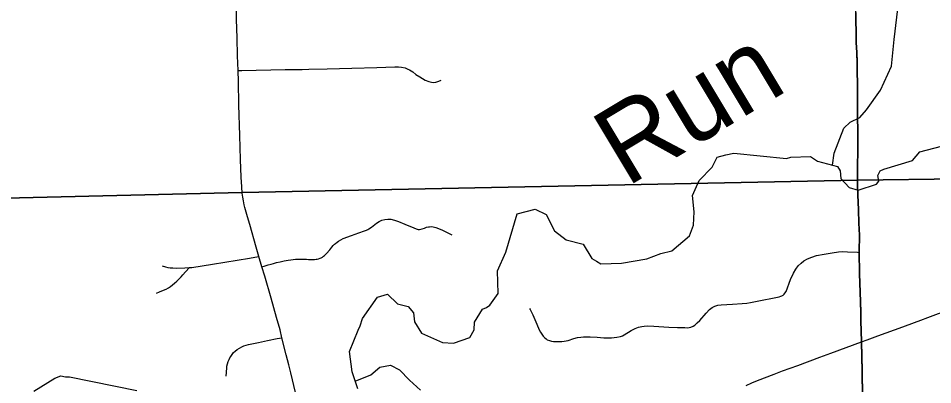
# Model space of a CAD drawing. Extents: x -6.4 to 34, y -4.2 to 22.
# Drawn here: x 5.927 to 7.044, y 20.413 to 20.86 of the extents above; entities that cross this region are included whole.
import ezdxf

# ---------------------------------------------------------------- set-up
doc = ezdxf.new("R2010")
doc.units = 0
for name, color, linetype in [('GM_X_Corporation', 7, 'Continuous'), ('GM_X_County_Road', 7, 'Continuous'), ('GM_X_Minor_River', 7, 'Continuous'), ('GM_X_Minor_River_Text', 7, 'Continuous'), ('GM_X_Township_Road', 7, 'Continuous')]:
    doc.layers.add(name, color=color, linetype=linetype)

msp = doc.modelspace()

# ---------------------------------------------------------------- linework, layer by layer
at = {"layer": 'GM_X_Corporation'}
for points in [[(5.4344, 20.629), (6.2003, 20.6471), (6.9525, 20.6623), (6.9525, 20.6735), (6.9527, 20.7036), (6.9526, 20.7219), (6.9525, 20.7397), (6.9524, 20.7675), (6.9522, 20.78), (6.9519, 20.7949), (6.9517, 20.8061), (6.9513, 20.8179), (6.9508, 20.8304), (6.9505, 20.8437), (6.9503, 20.8563), (6.9501, 20.8668), (6.9499, 20.8761), (6.9496, 20.886), (6.9493, 20.8922), (6.9492, 20.8965), (6.9491, 20.9), (2.1, 20.9)], [(6.9501, 20.8668), (6.9503, 20.8563), (6.9505, 20.8437), (6.9508, 20.8304), (6.9513, 20.8179), (6.9517, 20.8061), (6.9519, 20.7949), (6.9522, 20.78), (6.9524, 20.7675), (6.9525, 20.7397), (6.9526, 20.7219), (6.9527, 20.7036), (6.9525, 20.6735), (6.9525, 20.6623), (7.3276, 20.6671)], [(6.9584, 20.3986), (6.9578, 20.429), (6.9571, 20.4653), (6.9564, 20.4906), (6.9562, 20.5009), (6.9558, 20.514), (6.9549, 20.5481), (6.9545, 20.5746), (6.9546, 20.5952), (6.9541, 20.6099), (6.9535, 20.6262), (6.9528, 20.6443), (6.9525, 20.6571), (6.9525, 20.6623), (6.2003, 20.6471), (5.4344, 20.629)], [(7.3276, 20.6671), (6.9525, 20.6623), (6.9525, 20.6571), (6.9528, 20.6443), (6.9535, 20.6262), (6.9541, 20.6099), (6.9546, 20.5952), (6.9545, 20.5746), (6.9549, 20.5481), (6.9558, 20.514), (6.9562, 20.5009), (6.9564, 20.4906), (6.9571, 20.4653), (6.9578, 20.429), (6.9584, 20.3986)]]:
    msp.add_lwpolyline(points, dxfattribs=at)
at = {"layer": 'GM_X_County_Road'}
for points in [[(7.033, 20.4926), (7.0348, 20.4933), (7.0686, 20.506), (7.1085, 20.5212), (7.1624, 20.5408), (7.1749, 20.5452), (7.1812, 20.5473), (7.1875, 20.5496), (7.1944, 20.5522), (7.2027, 20.5556), (7.2113, 20.5597), (7.2192, 20.5638), (7.2292, 20.5695), (7.2385, 20.5759), (7.248, 20.582), (7.2572, 20.5884), (7.2748, 20.6012), (7.2872, 20.61), (7.2985, 20.6173), (7.3094, 20.6239), (7.3208, 20.6298), (7.329, 20.6338), (7.3327, 20.6357), (7.3446, 20.6412)], [(6.9573, 20.4647), (6.9643, 20.4673), (6.9771, 20.4721), (7.0075, 20.4831), (7.033, 20.4926)], [(6.8164, 20.4115), (6.823, 20.4147), (6.8301, 20.4176), (6.8503, 20.4255), (6.8608, 20.4294), (6.8795, 20.4362), (6.9063, 20.4462), (6.9198, 20.4511), (6.9573, 20.4647)]]:
    msp.add_lwpolyline(points, dxfattribs=at)
at = {"layer": 'GM_X_Minor_River'}
for points in [[(6.9218, 20.6806), (6.9238, 20.6952), (6.9354, 20.7258), (6.9433, 20.7331), (6.9553, 20.7387), (6.9635, 20.7479), (6.9805, 20.7721), (6.9937, 20.8016), (6.9969, 20.8339), (7.0043, 20.8959), (7.0061, 20.9)], [(6.5822, 20.6006), (6.5964, 20.5895), (6.6169, 20.5841), (6.6278, 20.5668), (6.6332, 20.5635), (6.6385, 20.5602), (6.6639, 20.561), (6.6949, 20.5664), (6.7122, 20.5728), (6.7254, 20.5761), (6.7471, 20.5943), (6.7521, 20.6073), (6.7526, 20.6236), (6.7508, 20.6437), (6.7588, 20.6617), (6.7749, 20.6783), (6.7807, 20.6902), (6.7913, 20.693), (6.8011, 20.6951), (6.8656, 20.6886), (6.8709, 20.6902), (6.8947, 20.6913), (6.9035, 20.6854), (6.9279, 20.679), (6.9313, 20.6737), (6.9319, 20.6642), (6.9423, 20.6534), (6.9533, 20.6502), (6.9755, 20.6574), (6.9785, 20.6612), (6.9773, 20.668), (6.9798, 20.6738), (6.9843, 20.6757), (7.0194, 20.6862), (7.0283, 20.697), (7.0551, 20.7039)], [(6.3418, 20.4075), (6.335, 20.4283), (6.3316, 20.4529), (6.3421, 20.4793), (6.3447, 20.4846), (6.3476, 20.4934), (6.3657, 20.5195), (6.3782, 20.5232), (6.3901, 20.5112), (6.4034, 20.508), (6.4096, 20.5002), (6.4109, 20.4892), (6.4195, 20.4756), (6.4454, 20.4639), (6.4587, 20.4634), (6.4786, 20.4702), (6.4838, 20.4797), (6.4844, 20.4889), (6.494, 20.5046), (6.4989, 20.507), (6.503, 20.5097), (6.5134, 20.5239), (6.5125, 20.5516), (6.5228, 20.5742), (6.5364, 20.6211), (6.5583, 20.6268), (6.5717, 20.6202), (6.5822, 20.6006)], [(6.3387, 20.417), (6.3578, 20.4245), (6.3686, 20.4338), (6.3815, 20.4363), (6.3925, 20.4308), (6.4049, 20.4181), (6.4183, 20.4061)], [(5.946, 20.4047), (5.9715, 20.4207), (5.9787, 20.4235), (5.9844, 20.422), (5.9893, 20.4221), (6.0718, 20.4053)]]:
    msp.add_lwpolyline(points, dxfattribs=at)
at = {"layer": 'GM_X_Township_Road'}
for points in [[(6.2005, 20.6465), (6.2001, 20.654), (6.1994, 20.6658), (6.1986, 20.6876), (6.1976, 20.7167), (6.1965, 20.754), (6.1958, 20.7825), (6.1955, 20.796), (6.1948, 20.8141), (6.1942, 20.8359), (6.1936, 20.8584), (6.193, 20.8795), (6.1924, 20.9)], [(6.9527, 20.6618), (6.9527, 20.6729), (6.9529, 20.703), (6.9528, 20.7213), (6.9527, 20.7392), (6.9526, 20.7669), (6.9523, 20.7795), (6.9521, 20.7944), (6.9519, 20.8055), (6.9515, 20.8173), (6.951, 20.8298), (6.9507, 20.8431), (6.9505, 20.8557), (6.9503, 20.8663), (6.9501, 20.8756), (6.9498, 20.8855), (6.9495, 20.8917), (6.9494, 20.896), (6.9493, 20.9)], [(6.1955, 20.796), (6.2001, 20.7962), (6.2531, 20.7975), (6.2739, 20.7975), (6.2819, 20.7976), (6.3045, 20.7983), (6.3345, 20.7991), (6.365, 20.7999), (6.3868, 20.8005), (6.3913, 20.8004), (6.3951, 20.8001), (6.3996, 20.7992), (6.4029, 20.7979), (6.4048, 20.7969), (6.4089, 20.7943), (6.4128, 20.7914), (6.4175, 20.7883), (6.424, 20.7845), (6.4286, 20.7826), (6.4316, 20.7818), (6.434, 20.7816), (6.4371, 20.7819), (6.4407, 20.783), (6.4435, 20.7843)], [(6.9573, 20.4647), (6.9566, 20.4901), (6.9564, 20.5004), (6.956, 20.5134), (6.9551, 20.5476), (6.9547, 20.5741), (6.9548, 20.5946), (6.9543, 20.6094), (6.9537, 20.6257), (6.953, 20.6437), (6.9527, 20.6565), (6.9527, 20.6618)], [(6.2685, 20.3896), (6.2655, 20.4032), (6.2599, 20.4269), (6.2573, 20.4369), (6.2541, 20.4489), (6.249, 20.4698), (6.2467, 20.4795), (6.2425, 20.4947), (6.236, 20.5181), (6.228, 20.5449), (6.2244, 20.5563), (6.2209, 20.5689), (6.2177, 20.5806), (6.2098, 20.6081), (6.2071, 20.6175), (6.2038, 20.629), (6.203, 20.6322), (6.2019, 20.6369), (6.2011, 20.6416), (6.2005, 20.6465)], [(6.2244, 20.5563), (6.2272, 20.5572), (6.2324, 20.5589), (6.2358, 20.5599), (6.2387, 20.5607), (6.2422, 20.5617), (6.2468, 20.5626), (6.2516, 20.5636), (6.2566, 20.5645), (6.2599, 20.565), (6.2657, 20.5657), (6.2685, 20.5659), (6.2722, 20.566), (6.2761, 20.5659), (6.2792, 20.5657), (6.2813, 20.5656), (6.2838, 20.5654), (6.2872, 20.5655), (6.2889, 20.5655), (6.2908, 20.5657), (6.292, 20.566), (6.2938, 20.5664), (6.2957, 20.5671), (6.297, 20.5676), (6.2985, 20.5684), (6.2997, 20.5693), (6.301, 20.5702), (6.3034, 20.5726), (6.3077, 20.5773), (6.3102, 20.5805), (6.3117, 20.5823), (6.3134, 20.5841), (6.3144, 20.5849), (6.3166, 20.5866), (6.3182, 20.5878), (6.3209, 20.5895), (6.3239, 20.5909), (6.3341, 20.5948), (6.3428, 20.598), (6.3499, 20.6005), (6.3522, 20.6013), (6.354, 20.6022), (6.3552, 20.6029), (6.3584, 20.6048), (6.3647, 20.6099), (6.3679, 20.6119), (6.3712, 20.6133), (6.3748, 20.6143), (6.3785, 20.6147), (6.3822, 20.6145), (6.3864, 20.6136), (6.3916, 20.6116), (6.3991, 20.6086), (6.4103, 20.6041), (6.4129, 20.6029), (6.4142, 20.6024), (6.4155, 20.6021), (6.4163, 20.602), (6.4172, 20.6021), (6.4188, 20.6025), (6.4203, 20.6029), (6.4232, 20.6038), (6.4257, 20.6047), (6.4281, 20.6051), (6.4293, 20.6054), (6.4314, 20.6056), (6.4338, 20.6052), (6.437, 20.6045), (6.4404, 20.6034), (6.4452, 20.6012), (6.4568, 20.5954)], [(6.5515, 20.5055), (6.5522, 20.5045), (6.5554, 20.4977), (6.5604, 20.4864), (6.5635, 20.4796), (6.5648, 20.4767), (6.5664, 20.4742), (6.5682, 20.4718), (6.5697, 20.4701), (6.5718, 20.4685), (6.5733, 20.4675), (6.5761, 20.4665), (6.5784, 20.4659), (6.5809, 20.4655), (6.5835, 20.4653), (6.5877, 20.4653), (6.5912, 20.4654), (6.594, 20.4657), (6.5964, 20.466), (6.5989, 20.4665), (6.6059, 20.4691), (6.6101, 20.4702), (6.6142, 20.4708), (6.6175, 20.4711), (6.6255, 20.4711), (6.6342, 20.4704), (6.6423, 20.4699), (6.6516, 20.4698), (6.6584, 20.4704), (6.6626, 20.4714), (6.6651, 20.4723), (6.6672, 20.4734), (6.6757, 20.4786), (6.6806, 20.4812), (6.6847, 20.4827), (6.6889, 20.4837), (6.6917, 20.4841), (6.6962, 20.4843), (6.7033, 20.4841), (6.7218, 20.483), (6.7325, 20.4824), (6.7415, 20.4822), (6.7444, 20.4821), (6.7467, 20.4823), (6.7488, 20.4828), (6.7514, 20.484), (6.7536, 20.4854), (6.7565, 20.4881), (6.7596, 20.4911), (6.7673, 20.5), (6.7716, 20.5045), (6.7746, 20.5067), (6.7779, 20.5084), (6.7815, 20.5095), (6.7858, 20.5102), (6.7994, 20.5108), (6.8112, 20.5116), (6.8169, 20.5121), (6.8215, 20.5128), (6.8278, 20.514), (6.8564, 20.5199), (6.8585, 20.5205), (6.86, 20.5211), (6.8614, 20.522), (6.8625, 20.5229), (6.8637, 20.5242), (6.865, 20.5263), (6.8706, 20.5408), (6.8742, 20.5488), (6.877, 20.5536), (6.88, 20.5576), (6.8835, 20.5611), (6.8869, 20.5637), (6.8912, 20.5662), (6.8964, 20.5684), (6.9024, 20.5701), (6.9117, 20.572), (6.9213, 20.5736), (6.9291, 20.5747), (6.9337, 20.575), (6.9399, 20.5749), (6.9525, 20.5742), (6.9547, 20.5741)], [(6.1027, 20.5577), (6.1067, 20.5564), (6.1096, 20.5557), (6.1124, 20.5554), (6.1156, 20.5552), (6.1205, 20.555), (6.1304, 20.5551), (6.136, 20.5555), (6.1391, 20.5558), (6.1642, 20.5596), (6.2096, 20.567), (6.2161, 20.5681), (6.2209, 20.5689)], [(6.0959, 20.5245), (6.0995, 20.5259), (6.1042, 20.5278), (6.1075, 20.5293), (6.1103, 20.5309), (6.1128, 20.5326), (6.1152, 20.5343), (6.1179, 20.5365), (6.1205, 20.5389), (6.1233, 20.5417), (6.1258, 20.5443), (6.1278, 20.5467), (6.1314, 20.5505), (6.136, 20.5555)], [(6.1811, 20.4228), (6.1813, 20.4274), (6.1817, 20.4335), (6.1819, 20.4353), (6.1824, 20.4382), (6.1833, 20.441), (6.1844, 20.4434), (6.1854, 20.4452), (6.1866, 20.4472), (6.1881, 20.4493), (6.1899, 20.4518), (6.192, 20.4536), (6.1944, 20.4555), (6.197, 20.4572), (6.2001, 20.4588), (6.2025, 20.46), (6.2053, 20.4609), (6.2082, 20.4617), (6.2122, 20.4625), (6.2203, 20.4641), (6.2315, 20.4665), (6.2433, 20.4688), (6.249, 20.4698)], [(6.9718, 19.7668), (6.9716, 19.7758), (6.9703, 19.8274), (6.9685, 19.9007), (6.9681, 19.9261), (6.9672, 19.9733), (6.9668, 19.99), (6.966, 20.0236), (6.9649, 20.0597), (6.9647, 20.0846), (6.9634, 20.1528), (6.9629, 20.1689), (6.962, 20.209), (6.9614, 20.2453), (6.9608, 20.2745), (6.9601, 20.3074), (6.9597, 20.3322), (6.9594, 20.3601), (6.9586, 20.398), (6.958, 20.4285), (6.9573, 20.4647)]]:
    msp.add_lwpolyline(points, dxfattribs=at)

# ---------------------------------------------------------------- texts
at = {"layer": 'GM_X_Minor_River_Text'}
msp.add_text('Run', height=0.09475, rotation=30.984, dxfattribs=at).set_placement((6.6699, 20.6531))

doc.saveas('drawing.dxf')
